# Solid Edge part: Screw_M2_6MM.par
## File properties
Author: hhakima
Template: Normal.par
Last saved by: hhakima
Revision: 5
Application: Solid Edge
Density: 7833.000 kg/m^3
Accuracy: 0.990
Material: Steel
Face Style: Steel
Fill Style: ANSI32(Steel)
Virtual Style: Machined steel
Coef. of Thermal Exp: 1.3e-05
Thermal Conductivity: 32.0
Specific Heat: 481.0
Modulus of Elasticity: 199947953000.0
Poission's Ratio: 0.29
Yield Stress: 262000766.0
Ultimate Stress: 358527364.0
Elongation: 0.0
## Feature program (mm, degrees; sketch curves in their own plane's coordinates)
body "unnamed Body 1"
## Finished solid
Body 1: solid body, 24 faces, 41 edges, 20 vertices.
  Faces by surface: plane 10, cone 9, cylinder 3, spline 2
  Edges by curve: circle 15, line 12, intersection 10, spline 4
Bounding box of the edges (mm; curved faces can reach further): 3.800 x 3.800 x 8.000, from (-1.9, -1.9, -8) to (1.9, 1.9, 0).
Cylindrical faces by radius (mm): R0.7402 x1, R1 x1, R1.9 x1
Conical faces (half-angle, radius in mm at the cone's reference point): 45 deg R0.866 x6, 45 deg R1.71 x1, 45 deg R1.9 x1, 55 deg R0.4862 x1
Planar faces by outward normal: +x 1, +z 2, -x 1, -z 2, oblique 4
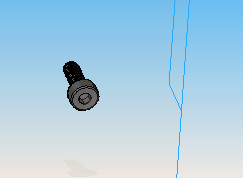
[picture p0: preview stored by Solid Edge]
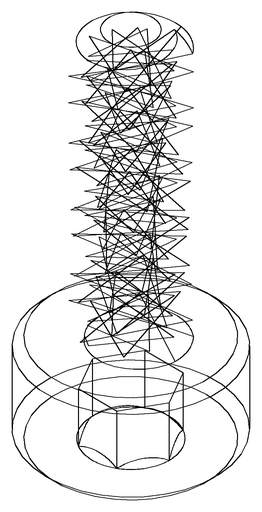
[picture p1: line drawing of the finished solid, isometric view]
